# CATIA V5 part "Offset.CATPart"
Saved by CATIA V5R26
Part number: Offset
Bounding box of the stored display mesh (mm): x -54.121 to 194.292, y -187.621 to 52.736, z -3.113 to 78.848
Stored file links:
  D:\LinkedIn Learning\NURBS\CATIA\Class Parts\Offset.CATPart
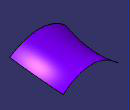
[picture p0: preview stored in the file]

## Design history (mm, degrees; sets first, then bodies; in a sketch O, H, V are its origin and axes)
AxisSystem1: origin (0, 0, 0), X (1, 0, 0), Y (0, 1, 0), Z (0, 0, 1)
Set1
  DatumSurface1
Body1 (main body)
